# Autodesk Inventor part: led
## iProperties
Created: 2011-01
Part Number: led
Document SubType Name: Modeling
Designer: eric
Density: 1 g/cm^3
Mass: 0.146477 g
Surface Area: 1.52371 cm^2
Volume: 0.146477 cm^3
Author: eric
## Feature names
1. Base1
